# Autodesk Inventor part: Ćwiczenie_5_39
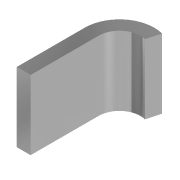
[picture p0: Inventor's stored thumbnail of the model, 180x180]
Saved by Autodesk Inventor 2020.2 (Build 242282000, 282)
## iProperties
Created: 2005-04
Part Number: Ćwiczenie_5_39
Document SubType Name: Modeling
Designer: F.Stasiak
Manufacturer: Standard
Standards Organization: Custom
Density: 1 g/cm^3
Material: Ogólny
Appearance: Chrom — polerowany
Manager: www.cadconsulting.pl
Company: Fabian Stasiak CAD Consulting
Author: F.Stasiak
Subject: Zbiór ćwiczeń. Autodesk Inventor 2020. Kurs podstawowy
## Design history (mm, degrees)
sketch "Szkic1"
  geometry: L1 (-4.899, -1)-(4.899, -1); L2 (4.899, 1)-(-4.899, 1); L3 (-4.899, 1)-(-4.899, -1); L4 (7.797, -4.776)-(9.729, -5.294); A1 r 5 centre (0, 0) between (-4.899, -1) and (4.899, 1); A2 r 3 centre (4.899, -4) between (7.797, -4.776) and (4.899, -1); A3 r 5 centre (4.899, -4) between (9.729, -5.294) and (4.899, 1); 1 further point
  constraints: 8 end point, 6 point on circle, 3 centre point, 2 tangent, 1 coincident, 1 concentric, 1 horizontal, 1 parallel, 1 perpendicular
  dimensions: "d0" = 10 diameter of A1; "d1" = 2 distance of L2.end L1.start; "d2" = 1 distance from line of L1 point (0, 0) (= 0.5 x d1); "d8" = 5 radius of A3; "d26" = 2 distance of L4.start L4.end; "d35" = 15 deg angle of L1 L4
extrude "Wyciągnięcie proste1" new body sketch "Szkic1" distance "d3" = 10; taper "d4" = 0 deg
node "Bryła1"
node "Korpusy bryłowe"
node "Korpusy powierzchniowe"
